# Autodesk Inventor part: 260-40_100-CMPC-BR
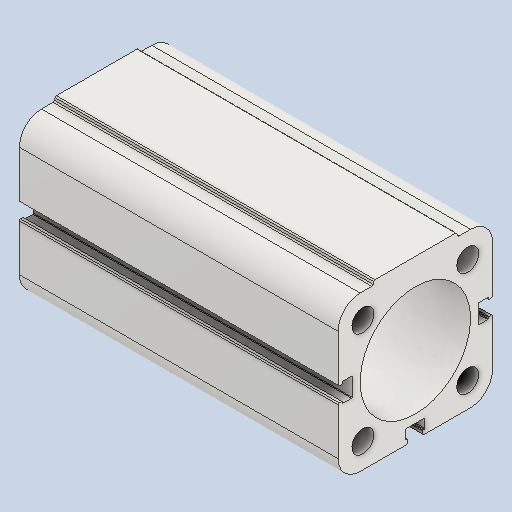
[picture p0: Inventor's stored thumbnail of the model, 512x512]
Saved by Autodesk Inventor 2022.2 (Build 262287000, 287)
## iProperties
Created: 2024-10
Part Number: 260-40_100-CMPC-BR
Material: Acciaio
Document SubType Name: Modeling
Designer: 18907419
Density: 7.85 g/cm^3
Appearance: Default
Author: 18907419
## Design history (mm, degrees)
feature "Solid1"
node "Solido1"
